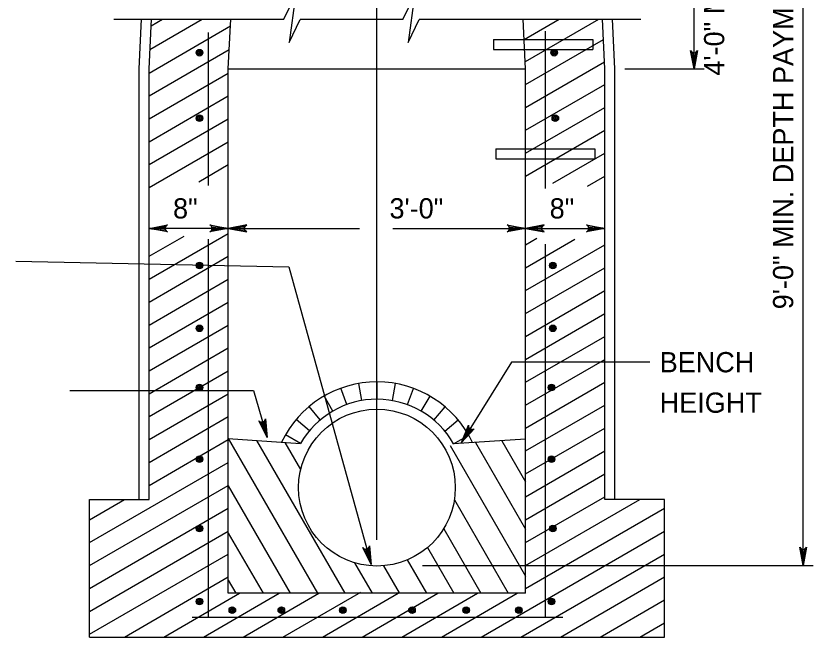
# Model space of a CAD drawing. Extents: x 0.9 to 8, y -0.9 to 9.3.
# Drawn here: x 4.981 to 7.346, y 1.611 to 3.453 of the extents above; entities that cross this region are included whole.
import ezdxf

# ---------------------------------------------------------------- set-up
doc = ezdxf.new("R2010")
doc.units = 0
for name, color, linetype in [('DETL-DIMS', 7, 'Continuous'), ('DETL-LINE', 7, 'Continuous'), ('DETL-NOTE', 7, 'Continuous'), ('DETL-PATT', 7, 'Continuous')]:
    doc.layers.add(name, color=color, linetype=linetype)

msp = doc.modelspace()

# ---------------------------------------------------------------- linework, layer by layer
at = {"layer": 'DETL-DIMS'}
for p, q in [((7.3166, 1.8231), (7.3166, 4.7566)), ((6.0519, 1.8996), (6.0519, 4.5023)), ((6.9931, 3.2959), (6.9931, 4.4723)), ((6.7873, 3.2959), (7.0225, 3.2959)), ((5.6108, 2.823), (5.3755, 2.823)), ((5.6108, 2.823), (6.0006, 2.823)), ((6.0992, 2.823), (6.4931, 2.823)), ((6.4931, 2.823), (6.7284, 2.823)), ((4.9807, 2.7254), (5.7909, 2.7085)), ((5.7909, 2.7085), (6.035, 1.8265)), ((6.4511, 2.4263), (6.3029, 2.1879)), ((6.8615, 2.4263), (6.4511, 2.4263)), ((5.1408, 2.3421), (5.6858, 2.3421)), ((5.6858, 2.3421), (5.7265, 2.2031)), ((6.1871, 1.8231), (7.346, 1.8231))]:
    msp.add_line(p, q, dxfattribs=at)
for points in [[(6.9931, 3.2959), (6.9828, 3.3507), (6.9858, 3.3465), (6.9894, 3.3443), (6.9931, 3.3437), (6.9968, 3.3443), (7.0005, 3.3465), (7.0034, 3.3507), (6.9931, 3.2959), (7.0005, 3.3465), (6.9968, 3.3443), (6.9931, 3.2959), (6.9931, 3.3437), (6.9894, 3.3443), (6.9931, 3.2959), (6.9858, 3.3465)], [(5.3755, 2.823), (5.4303, 2.8333), (5.4261, 2.8304), (5.4239, 2.8267), (5.4233, 2.823), (5.4239, 2.8193), (5.4261, 2.8157), (5.4303, 2.8127), (5.3755, 2.823), (5.4261, 2.8157), (5.4239, 2.8193), (5.3755, 2.823), (5.4233, 2.823), (5.4239, 2.8267), (5.3755, 2.823), (5.4261, 2.8304)], [(5.6108, 2.823), (5.5559, 2.8127), (5.5601, 2.8157), (5.5623, 2.8193), (5.563, 2.823), (5.5623, 2.8267), (5.5601, 2.8304), (5.5559, 2.8333), (5.6108, 2.823), (5.5601, 2.8304), (5.5623, 2.8267), (5.6108, 2.823), (5.563, 2.823), (5.5623, 2.8193), (5.6108, 2.823), (5.5601, 2.8157)], [(5.6108, 2.823), (5.6656, 2.8127), (5.6614, 2.8157), (5.6592, 2.8193), (5.6585, 2.823), (5.6592, 2.8267), (5.6614, 2.8304), (5.6656, 2.8333), (5.6108, 2.823), (5.6614, 2.8304), (5.6592, 2.8267), (5.6108, 2.823), (5.6585, 2.823), (5.6592, 2.8193), (5.6108, 2.823), (5.6614, 2.8157)], [(6.4931, 2.823), (6.4383, 2.8127), (6.4425, 2.8157), (6.4447, 2.8193), (6.4453, 2.823), (6.4447, 2.8267), (6.4425, 2.8304), (6.4383, 2.8333), (6.4931, 2.823), (6.4425, 2.8304), (6.4447, 2.8267), (6.4931, 2.823), (6.4453, 2.823), (6.4447, 2.8193), (6.4931, 2.823), (6.4425, 2.8157)], [(6.4931, 2.823), (6.5479, 2.8127), (6.5437, 2.8157), (6.5415, 2.8193), (6.5409, 2.823), (6.5415, 2.8267), (6.5437, 2.8304), (6.5479, 2.8333), (6.4931, 2.823), (6.5437, 2.8304), (6.5415, 2.8267), (6.4931, 2.823), (6.5409, 2.823), (6.5415, 2.8193), (6.4931, 2.823), (6.5437, 2.8157)], [(6.7284, 2.823), (6.6736, 2.8127), (6.6778, 2.8157), (6.68, 2.8193), (6.6806, 2.823), (6.68, 2.8267), (6.6778, 2.8304), (6.6736, 2.8333), (6.7284, 2.823), (6.6778, 2.8304), (6.68, 2.8267), (6.7284, 2.823), (6.6806, 2.823), (6.68, 2.8193), (6.7284, 2.823), (6.6778, 2.8157)], [(5.7265, 2.2031), (5.7012, 2.2528), (5.7052, 2.2496), (5.7094, 2.2485), (5.7131, 2.2489), (5.7164, 2.2506), (5.7193, 2.2537), (5.721, 2.2586), (5.7265, 2.2031), (5.7193, 2.2537), (5.7164, 2.2506), (5.7265, 2.2031), (5.7131, 2.2489), (5.7094, 2.2485), (5.7265, 2.2031), (5.7052, 2.2496)], [(6.3029, 2.1879), (6.3231, 2.2398), (6.3234, 2.2347), (6.3253, 2.2309), (6.3281, 2.2284), (6.3316, 2.227), (6.3359, 2.2269), (6.3406, 2.229), (6.3029, 2.1879), (6.3359, 2.2269), (6.3316, 2.227), (6.3029, 2.1879), (6.3281, 2.2284), (6.3253, 2.2309), (6.3029, 2.1879), (6.3234, 2.2347)], [(6.035, 1.8265), (6.0105, 1.8766), (6.0144, 1.8733), (6.0185, 1.8722), (6.0222, 1.8726), (6.0256, 1.8742), (6.0286, 1.8773), (6.0303, 1.8821), (6.035, 1.8265), (6.0286, 1.8773), (6.0256, 1.8742), (6.035, 1.8265), (6.0222, 1.8726), (6.0185, 1.8722), (6.035, 1.8265), (6.0144, 1.8733)], [(7.3166, 1.8231), (7.3064, 1.8779), (7.3093, 1.8737), (7.313, 1.8715), (7.3166, 1.8709), (7.3203, 1.8715), (7.324, 1.8737), (7.3269, 1.8779), (7.3166, 1.8231), (7.324, 1.8737), (7.3203, 1.8715), (7.3166, 1.8231), (7.3166, 1.8709), (7.313, 1.8715), (7.3166, 1.8231), (7.3093, 1.8737)]]:
    msp.add_lwpolyline(points, dxfattribs=at)
at = {"layer": 'DETL-LINE'}
for p, q in [((5.2711, 3.4429), (5.7752, 3.4429)), ((5.346, 3.2959), (5.3534, 3.4429)), ((5.3755, 3.2959), (5.3828, 3.4429)), ((5.6108, 3.2959), (5.6181, 3.4429)), ((5.8237, 3.4429), (6.1288, 3.4429)), ((6.1773, 3.4429), (6.8354, 3.4429)), ((6.4931, 3.2959), (6.4858, 3.4429)), ((6.7284, 3.2959), (6.721, 3.4429)), ((6.7578, 3.2959), (6.7505, 3.4429)), ((6.5519, 2.9415), (6.5519, 3.4073)), ((5.5519, 2.9504), (5.5519, 3.4036)), ((6.3982, 3.3826), (6.3982, 3.3532)), ((6.3982, 3.3826), (6.4888, 3.3826)), ((6.4888, 3.3826), (6.6923, 3.3826)), ((6.6923, 3.3826), (6.6923, 3.3532)), ((6.3982, 3.3532), (6.4902, 3.3532)), ((6.4902, 3.3532), (6.6923, 3.3532)), ((5.346, 2.0189), (5.346, 3.2959)), ((5.3755, 2.0189), (5.3755, 3.2959)), ((5.6108, 3.2959), (6.4931, 3.2959)), ((5.6108, 1.741), (5.6108, 3.2959)), ((6.4931, 1.741), (6.4931, 3.2959)), ((6.7284, 2.0189), (6.7284, 3.2959)), ((6.7578, 2.0189), (6.7578, 3.2959)), ((6.4048, 3.0591), (6.4048, 3.0297)), ((6.4048, 3.0591), (6.4931, 3.0591)), ((6.4931, 3.0591), (6.6989, 3.0591)), ((6.6989, 3.0591), (6.6989, 3.0297)), ((6.4048, 3.0297), (6.4931, 3.0297)), ((6.4931, 3.0297), (6.6989, 3.0297)), ((5.5519, 1.6701), (5.5519, 2.7908)), ((6.5519, 1.6701), (6.5519, 2.7766)), ((6.2533, 2.2221), (6.2928, 2.255)), ((5.6108, 2.1997), (5.825, 2.1854)), ((6.4931, 2.1978), (6.2794, 2.1845)), ((5.199, 1.6113), (5.199, 2.0189)), ((5.199, 2.0189), (5.3755, 2.0189)), ((6.9049, 2.0189), (6.7284, 2.0189)), ((6.9049, 1.6113), (6.9049, 2.0189)), ((6.4931, 1.741), (5.6108, 1.741)), ((5.5034, 1.6701), (6.6036, 1.6701)), ((5.199, 1.6113), (6.9049, 1.6113))]:
    msp.add_line(p, q, dxfattribs=at)
for points in [[(5.7751, 3.4423), (5.81, 3.5138), (5.791, 3.3739), (5.8236, 3.4423)], [(6.1285, 3.4423), (6.1635, 3.5138), (6.1445, 3.3738), (6.177, 3.4423)]]:
    msp.add_lwpolyline(points, dxfattribs=at)
for centre, radius in [((5.5257, 3.3439), 0.0098), ((5.5257, 3.3439), 0.00735), ((5.5257, 3.3439), 0.0049), ((5.5257, 3.3439), 0.00245), ((6.5775, 3.3439), 0.0098), ((6.5775, 3.3439), 0.00735), ((6.5775, 3.3439), 0.0049), ((6.5775, 3.3439), 0.00245), ((5.5257, 3.1498), 0.0098), ((5.5257, 3.1498), 0.00735), ((5.5257, 3.1498), 0.0049), ((5.5257, 3.1498), 0.00245), ((6.5812, 3.1498), 0.0098), ((6.5812, 3.1498), 0.00735), ((6.5812, 3.1498), 0.0049), ((6.5812, 3.1498), 0.00245), ((5.5257, 2.7132), 0.0098), ((5.5257, 2.7132), 0.00735), ((6.5737, 2.7132), 0.0098), ((6.5737, 2.7132), 0.00735), ((5.5257, 2.7132), 0.0049), ((5.5257, 2.7132), 0.00245), ((6.5737, 2.7132), 0.0049), ((6.5737, 2.7132), 0.00245), ((5.5257, 2.5266), 0.0098), ((5.5257, 2.5266), 0.00735), ((5.5257, 2.5266), 0.0049), ((6.5737, 2.5266), 0.0098), ((6.5737, 2.5266), 0.00735), ((6.5737, 2.5266), 0.0049), ((5.5257, 2.5266), 0.00245), ((6.5737, 2.5266), 0.00245), ((5.5257, 2.3513), 0.0098), ((5.5257, 2.3513), 0.00735), ((5.5257, 2.3513), 0.0049), ((5.5257, 2.3513), 0.00245), ((6.57, 2.3513), 0.0098), ((6.57, 2.3513), 0.00735), ((6.57, 2.3513), 0.0049), ((6.57, 2.3513), 0.00245), ((6.0519, 2.0544), 0.2326), ((5.5257, 2.1385), 0.0098), ((5.5257, 2.1385), 0.00735), ((5.5257, 2.1385), 0.0049), ((5.5257, 2.1385), 0.00245), ((6.57, 2.1385), 0.0098), ((6.57, 2.1385), 0.00735), ((6.57, 2.1385), 0.0049), ((6.57, 2.1385), 0.00245), ((5.5257, 1.9333), 0.0098), ((5.5257, 1.9333), 0.00735), ((6.5737, 1.9333), 0.0098), ((6.5737, 1.9333), 0.00735), ((5.5257, 1.9333), 0.0049), ((5.5257, 1.9333), 0.00245), ((6.5737, 1.9333), 0.0049), ((6.5737, 1.9333), 0.00245), ((5.5257, 1.7169), 0.0098), ((5.5257, 1.7169), 0.00735), ((5.5257, 1.7169), 0.0049), ((5.5257, 1.7169), 0.00245), ((6.57, 1.7169), 0.0098), ((6.57, 1.7169), 0.00735), ((6.57, 1.7169), 0.0049), ((6.57, 1.7169), 0.00245), ((5.6227, 1.6907), 0.0098), ((5.6227, 1.6907), 0.00735), ((5.6227, 1.6907), 0.0049), ((5.6227, 1.6907), 0.00245), ((5.7682, 1.6907), 0.0098), ((5.7682, 1.6907), 0.00735), ((5.7682, 1.6907), 0.0049), ((5.7682, 1.6907), 0.00245), ((5.9509, 1.6907), 0.0098), ((5.9509, 1.6907), 0.00735), ((5.9509, 1.6907), 0.0049), ((5.9509, 1.6907), 0.00245), ((6.156, 1.6907), 0.0098), ((6.156, 1.6907), 0.00735), ((6.156, 1.6907), 0.0049), ((6.156, 1.6907), 0.00245), ((6.3164, 1.6907), 0.0098), ((6.3164, 1.6907), 0.00735), ((6.3164, 1.6907), 0.0049), ((6.3164, 1.6907), 0.00245), ((6.473, 1.6907), 0.0098), ((6.473, 1.6907), 0.00735), ((6.473, 1.6907), 0.0049), ((6.473, 1.6907), 0.00245)]:
    msp.add_circle(centre, radius, dxfattribs=at)
for radius, start, end in [(0.3135, 25.2164, 154.5471), (0.262, 29.758, 150.0059)]:
    msp.add_arc((6.0519, 2.0544), radius, start, end, dxfattribs=at)
at = {"layer": 'DETL-PATT'}
for p, q in [((5.3783, 3.3533), (5.5336, 3.4429)), ((5.3818, 3.4232), (5.4159, 3.4429)), ((6.4887, 3.3831), (6.5924, 3.4429)), ((6.4931, 3.3177), (6.71, 3.4429)), ((5.3755, 3.2837), (5.6171, 3.4232)), ((6.4931, 3.2497), (6.724, 3.3831)), ((5.3755, 3.2158), (5.6136, 3.3533)), ((6.4931, 3.1818), (6.7273, 3.3171)), ((5.3755, 3.1479), (5.6108, 3.2837)), ((6.4931, 3.1139), (6.7284, 3.2497)), ((5.3755, 3.0799), (5.6108, 3.2158)), ((6.4931, 3.046), (6.7284, 3.1818)), ((5.3755, 3.012), (5.6108, 3.1479)), ((6.4931, 2.978), (6.7284, 3.1139)), ((5.3755, 2.9441), (5.6108, 3.0799)), ((6.5736, 2.9566), (6.7284, 3.046)), ((5.523, 2.9614), (5.6108, 3.012)), ((6.6763, 2.948), (6.7284, 2.9781)), ((5.3755, 2.6724), (5.6108, 2.8082)), ((5.3755, 2.7403), (5.4795, 2.8004)), ((6.4931, 2.7743), (6.5265, 2.7935)), ((6.4931, 2.7064), (6.6391, 2.7906)), ((6.4931, 2.6384), (6.7284, 2.7743)), ((5.3755, 2.6045), (5.6108, 2.7403)), ((6.4931, 2.5705), (6.7284, 2.7064)), ((5.3755, 2.5365), (5.6108, 2.6724)), ((6.4931, 2.5026), (6.7284, 2.6384)), ((5.3755, 2.4686), (5.6108, 2.6045)), ((6.4931, 2.4347), (6.7284, 2.5705)), ((5.3755, 2.4007), (5.6108, 2.5365)), ((6.4931, 2.3667), (6.7284, 2.5026)), ((5.3755, 2.3328), (5.6108, 2.4686)), ((6.4931, 2.2988), (6.7284, 2.4347)), ((5.3755, 2.2648), (5.6108, 2.4007)), ((6.0525, 2.3164), (6.0526, 2.3679)), ((6.4931, 2.2309), (6.7284, 2.3667)), ((5.9626, 2.3008), (5.9451, 2.3492)), ((6.0069, 2.3125), (5.998, 2.3632)), ((6.098, 2.3124), (6.1071, 2.363)), ((6.1422, 2.3004), (6.16, 2.3487)), ((5.3755, 2.1969), (5.6108, 2.3328)), ((5.9211, 2.2815), (5.8955, 2.3261)), ((6.1836, 2.2809), (6.2095, 2.3254)), ((5.8836, 2.2553), (5.8506, 2.2947)), ((6.4931, 2.163), (6.7284, 2.2988)), ((6.221, 2.2546), (6.2543, 2.2939)), ((5.3755, 2.129), (5.6108, 2.2648)), ((5.8513, 2.2229), (5.8118, 2.256)), ((6.4931, 2.095), (6.7284, 2.2309)), ((5.825, 2.1854), (5.7804, 2.2112)), ((6.2794, 2.1845), (6.3241, 2.21)), ((5.3755, 2.0611), (5.6108, 2.1969)), ((5.6108, 2.1997), (5.8756, 1.741)), ((5.6948, 2.1941), (5.9564, 1.741)), ((5.7789, 2.1885), (5.8255, 2.1077)), ((6.2695, 2.1788), (6.4931, 1.7914)), ((6.3446, 2.1886), (6.4931, 1.9314)), ((6.4227, 2.1934), (6.4931, 2.0714)), ((6.4931, 2.0271), (6.7284, 2.163)), ((5.199, 1.8913), (5.6108, 2.129)), ((6.4931, 1.9592), (6.7284, 2.095)), ((5.199, 1.8233), (5.6108, 2.0611)), ((5.6108, 2.0597), (5.7948, 1.741)), ((5.199, 1.9592), (5.3024, 2.0189)), ((6.2816, 2.0177), (6.4414, 1.741)), ((6.4931, 1.8913), (6.7284, 2.0271)), ((6.4931, 1.8233), (6.8318, 2.0189)), ((5.199, 1.7554), (5.6108, 1.9932)), ((6.4931, 1.7554), (6.9049, 1.9932)), ((5.199, 1.6875), (5.6108, 1.9252)), ((5.6108, 1.9197), (5.7139, 1.741)), ((6.25, 1.9325), (6.3606, 1.741)), ((6.3611, 1.6113), (6.9049, 1.9252)), ((6.2016, 1.8764), (6.2798, 1.741)), ((5.199, 1.6196), (5.6108, 1.8573)), ((6.4787, 1.6113), (6.9049, 1.8573)), ((5.9849, 1.8317), (6.0373, 1.741)), ((6.0709, 1.8226), (6.1174, 1.7423)), ((6.1418, 1.8399), (6.1989, 1.741)), ((5.3023, 1.6113), (5.6108, 1.7894)), ((5.6108, 1.7797), (5.6331, 1.741)), ((6.5964, 1.6113), (6.9049, 1.7894)), ((5.4199, 1.6113), (5.6445, 1.741)), ((5.5376, 1.6113), (5.7622, 1.741)), ((5.6552, 1.6113), (5.8798, 1.741)), ((5.7728, 1.6113), (6.0039, 1.7447)), ((5.8905, 1.6113), (6.1151, 1.741)), ((6.0081, 1.6113), (6.2328, 1.741)), ((6.1258, 1.6113), (6.3504, 1.741)), ((6.2434, 1.6113), (6.4681, 1.741)), ((6.714, 1.6113), (6.9049, 1.7215)), ((6.8317, 1.6113), (6.9049, 1.6535))]:
    msp.add_line(p, q, dxfattribs=at)

# ---------------------------------------------------------------- texts
at = {"layer": 'DETL-NOTE'}
for s, p in [('4\'-0" MAX. 3\'-0" MIN.', (7.0825, 3.2758)), ('9\'-0" MIN. DEPTH PAYMENT', (7.2872, 2.5831))]:
    msp.add_text(s, height=0.06, rotation=90, dxfattribs=at).set_placement(p)
for s, p in [('8"', (5.4468, 2.8524)), ('3\'-0"', (6.0891, 2.8524)), ('8"', (6.5644, 2.8524)), ('BENCH', (6.8909, 2.3963)), ('HEIGHT', (6.8909, 2.2763))]:
    msp.add_text(s, height=0.06, dxfattribs=at).set_placement(p)

doc.saveas('drawing.dxf')
